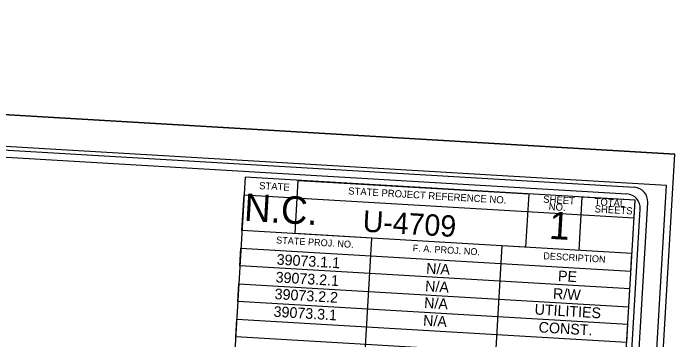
# Model space of a CAD drawing. Extents: x 1998567 to 2027801, y 439108 to 451079.
# Drawn here: x 2016563 to 2021220, y 448783 to 451079 of the extents above; entities that cross this region are included whole.
import ezdxf

# ---------------------------------------------------------------- set-up
doc = ezdxf.new("R2010")
doc.units = 0
for name, color, linetype in [('Sheet Cutting Line CELL', 7, 'Continuous'), ('Sheet Data Field CELL', 7, 'Continuous'), ('Sheet Plot Border Inside CELL', 7, 'Continuous'), ('Sheet Plot Border Outside CELL', 7, 'Continuous'), ('Sheet Title CELL', 7, 'Continuous')]:
    doc.layers.add(name, color=color, linetype=linetype)

msp = doc.modelspace()

# ---------------------------------------------------------------- linework, layer by layer
at = {"layer": 'Sheet Cutting Line CELL'}
msp.add_line((2004409.5, 451079.4), (2021220.3, 450088.4), dxfattribs=at)
at = {"layer": 'Sheet Plot Border Inside CELL'}
msp.add_lwpolyline([(2003905.2, 440314.9), (2020541.3, 439334.2), (2021162.2, 449866.9), (2004526.1, 450847.6)], close=True, dxfattribs=at)
at = {"layer": 'Sheet Plot Border Outside CELL'}
msp.add_lwpolyline([(2021220.3, 450088.4), (2004409.5, 451079.4), (2003762.2, 440098.6), (2020573, 439107.6)], close=True, dxfattribs=at)
at = {"layer": 'Sheet Title CELL'}
for points in [[(2020936.2, 449854.7), (2006161.6, 450725.8)], [(2020883.2, 449807.8), (2006707.9, 450643.4)], [(2020874.6, 448641.2), (2018129.4, 448803.1), (2018136.7, 448928), (2020881.9, 448766.2), (2020889.3, 448890.9), (2018144, 449052.8), (2018151.4, 449177.4), (2020896.6, 449015.7), (2020904, 449140.4), (2018158.7, 449302.2), (2018166.1, 449427), (2020911.3, 449265.2), (2020918.7, 449390.1), (2018173.5, 449551.9), (2018188.2, 449801.5), (2020933.4, 449639.6), (2020940.8, 449764.4), (2018195.5, 449926.1), (2018107.3, 448428.9)], [(2019022.2, 448374.8), (2019088.4, 449497.8), (2018547.8, 449529.7), (2018569.9, 449904.2), (2020192.2, 449808.4), (2020170, 449434.2), (2020003.3, 449444), (2019937.1, 448321)], [(2020852.5, 448267), (2020940.8, 449764.4), (2020566.4, 449786.5), (2020544.5, 449412.1)], [(2020423.9, 439467), (2021030, 449749)], [(2020485.8, 441366.5), (2020977.2, 449702.2)]]:
    msp.add_lwpolyline(points, dxfattribs=at)
for centre in [(2020930.3, 449755.5), (2020877.4, 449708.5)]:
    msp.add_arc(centre, 100, 356.6264, 86.6264, dxfattribs=at)

# ---------------------------------------------------------------- texts
at = {"layer": 'Sheet Data Field CELL'}
for s, height, p in [('U-4709', 150, (2019020.3, 449543.9)), ('39073.1.1', 75, (2018416.3, 449311.6)), ('N/A', 75, (2019468.8, 449249.5)), ('39073.2.1', 75, (2018408.9, 449186.8)), ('PE', 75, (2020396.6, 449195.8)), ('N/A', 75, (2019461.4, 449124.7)), ('39073.2.2', 75, (2018402, 449068.7)), ('R/W', 75, (2020361.3, 449071.8)), ('N/A', 75, (2019454.5, 449006.6)), ('39073.3.1', 75, (2018394.7, 448945)), ('UTILITIES', 75, (2020231.8, 448960.9)), ('N/A', 75, (2019447.2, 448883)), ('CONST.', 75, (2020260.5, 448835.1))]:
    msp.add_text(s, height=height, rotation=356.6264, dxfattribs=at).set_placement(p)
at = {"layer": 'Sheet Title CELL'}
for s, height, p in [('STATE', 50, (2018293.3, 449842.9)), ('STATE PROJECT REFERENCE NO.', 49.998, (2018920.7, 449805.7)), ('N.C.', 193.5, (2018185, 449619.8)), ('SHEET', 50, (2020293.1, 449747.4)), ('TOTAL', 50, (2020654.7, 449729.7)), ('NO.', 50, (2020331.7, 449695.6)), ('SHEETS', 50, (2020655.2, 449679.6)), ('1', 193.5, (2020332.3, 449493.3)), ('STATE PROJ. NO.', 48, (2018413, 449461.1)), ('F. A. PROJ. NO.', 48, (2019374.4, 449404.5)), ('DESCRIPTION', 48, (2020293.8, 449350.2))]:
    msp.add_text(s, height=height, rotation=356.6264, dxfattribs=at).set_placement(p)

doc.saveas('drawing.dxf')
